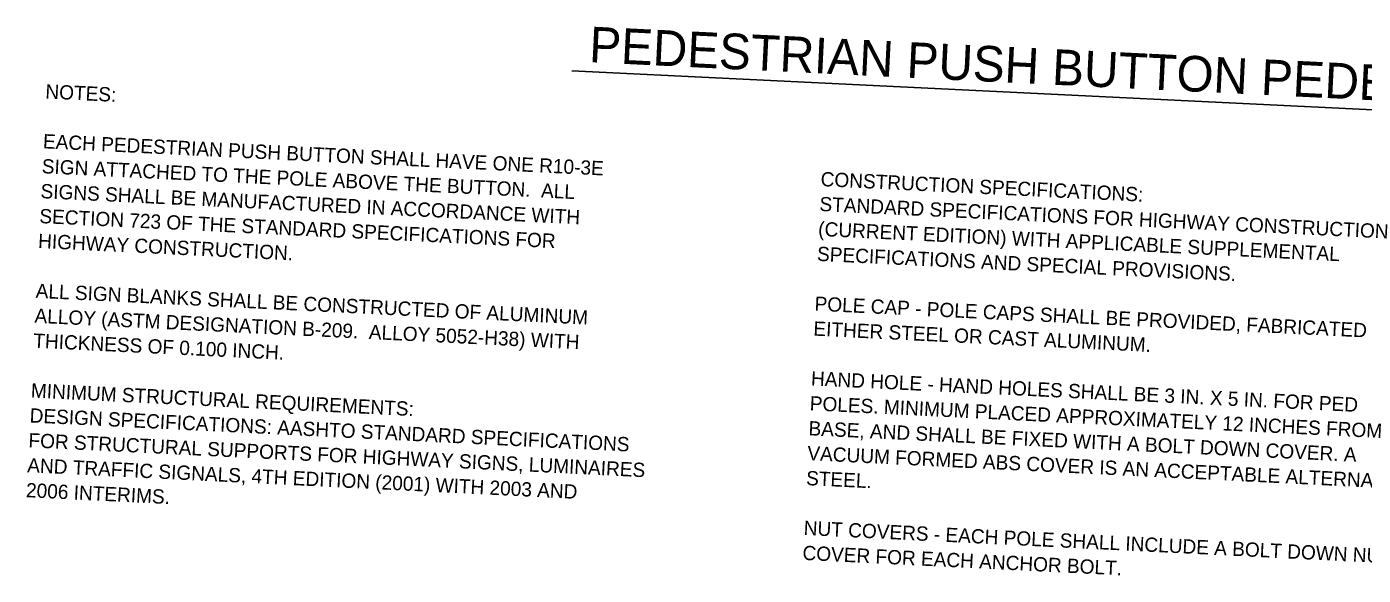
# Model space of a CAD drawing. Extents: x 661018 to 663325, y 642537 to 643074.
# Drawn here: x 661663.2 to 661979.1, y 642580.4 to 642710.1 of the extents above; entities that cross this region are included whole.
import ezdxf

# ---------------------------------------------------------------- set-up
doc = ezdxf.new("R2010")
doc.units = 0
doc.layers.add('R_Dimension', color=7, linetype='Continuous')

msp = doc.modelspace()

# ---------------------------------------------------------------- linework, layer by layer
at = {"layer": 'R_Dimension'}
msp.add_line((661791.98, 642699.65), (662084.41, 642685.45), dxfattribs=at)

# ---------------------------------------------------------------- texts
for s, height, p in [('PEDESTRIAN PUSH BUTTON PEDESTAL DETAIL', 8.4231, (661795.99, 642701.71)), ('NOTES:', 3.369, (661667.51, 642693.13)), ('EACH PEDESTRIAN PUSH BUTTON SHALL HAVE ONE R10-3E ', 3.3692, (661666.94, 642681.36)), ('SIGN ATTACHED TO THE POLE ABOVE THE BUTTON.  ALL ', 3.3692, (661666.65, 642675.47)), ('CONSTRUCTION SPECIFICATIONS:', 3.3692, (661850.76, 642672.43)), ('SIGNS SHALL BE MANUFACTURED IN ACCORDANCE WITH ', 3.3692, (661666.36, 642669.58)), ('STANDARD SPECIFICATIONS FOR HIGHWAY CONSTRUCTION ', 3.3692, (661850.48, 642666.54)), ('SECTION 723 OF THE STANDARD SPECIFICATIONS FOR ', 3.3692, (661666.08, 642663.69)), ('(CURRENT EDITION) WITH APPLICABLE SUPPLEMENTAL ', 3.3692, (661850.19, 642660.65)), ('HIGHWAY CONSTRUCTION.', 3.3692, (661665.79, 642657.8)), ('SPECIFICATIONS AND SPECIAL PROVISIONS.', 3.3692, (661849.91, 642654.76)), ('ALL SIGN BLANKS SHALL BE CONSTRUCTED OF ALUMINUM ', 3.3692, (661665.22, 642646.02)), ('POLE CAP - POLE CAPS SHALL BE PROVIDED, FABRICATED OF ', 3.3692, (661849.33, 642642.98)), ('ALLOY (ASTM DESIGNATION B-209.  ALLOY 5052-H38) WITH ', 3.3692, (661664.94, 642640.13)), ('EITHER STEEL OR CAST ALUMINUM.', 3.3692, (661849.05, 642637.09)), ('THICKNESS OF 0.100 INCH.', 3.3692, (661664.65, 642634.24)), ('HAND HOLE - HAND HOLES SHALL BE 3 IN. X 5 IN. FOR PED ', 3.3692, (661848.48, 642625.32)), ('MINIMUM STRUCTURAL REQUIREMENTS:', 3.3692, (661664.08, 642622.46)), ('POLES. MINIMUM PLACED APPROXIMATELY 12 INCHES FROM ', 3.3692, (661848.19, 642619.43)), ('DESIGN SPECIFICATIONS: AASHTO STANDARD SPECIFICATIONS ', 3.3692, (661663.79, 642616.57)), ('FOR STRUCTURAL SUPPORTS FOR HIGHWAY SIGNS, LUMINAIRES ', 3.3692, (661663.51, 642610.69)), ('BASE, AND SHALL BE FIXED WITH A BOLT DOWN COVER. A ', 3.3692, (661847.9, 642613.54)), ('VACUUM FORMED ABS COVER IS AN ACCEPTABLE ALTERNATE TO ', 3.3692, (661847.62, 642607.65)), ('AND TRAFFIC SIGNALS, 4TH EDITION (2001) WITH 2003 AND ', 3.3692, (661663.22, 642604.8)), ('STEEL. ', 3.369, (661847.33, 642601.76)), ('2006 INTERIMS.', 3.3692, (661662.93, 642598.91)), ('NUT COVERS - EACH POLE SHALL INCLUDE A BOLT DOWN NUT ', 3.3692, (661846.76, 642589.98)), ('COVER FOR EACH ANCHOR BOLT.', 3.3692, (661846.47, 642584.09))]:
    msp.add_text(s, height=height, rotation=357.2199, dxfattribs=at).set_placement(p)

doc.saveas('drawing.dxf')
